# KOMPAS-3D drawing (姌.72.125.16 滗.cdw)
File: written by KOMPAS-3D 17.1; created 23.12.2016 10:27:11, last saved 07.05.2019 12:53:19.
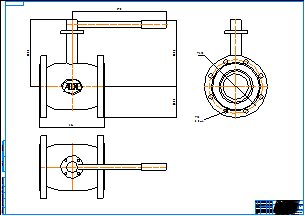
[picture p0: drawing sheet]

Sheet 1: A0, landscape

Title block, sheet 1: name: КШ.72.125.16 фф; material: Внимание! Данный продукт является объектом авторского права ООО «Торговый Дом АДЛ». / Запрещается изменение, копирование, распространение / (в том числе путем копирования на другие сайты и ресурсы в Интернете) / или любое иное использование информации и объектов без предварительного / согласия правообладателя (ООО «Торговый Дом АДЛ»).; sheets: 1; organisation: ООО "Торговый дом АДЛ"; sheet format: A0; stored path: C:\Users\tra\Desktop\2д чертежи\Шаровые краны БИВАЛ\КШ_Бивал_серия_72\KOMPAS_2D\КШ.72.125.16 фф.cdw

Views: Спереди 4, Проекционный вид 5, Проекционный вид 6
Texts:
  Klimkovich
  ADL
Dimensions and other numbers on the sheet: 254; 370; 258,4; 122,5; 260,9; 210; 18; 8 Отв.; 1:1; 1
